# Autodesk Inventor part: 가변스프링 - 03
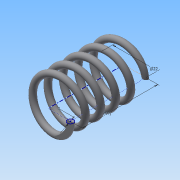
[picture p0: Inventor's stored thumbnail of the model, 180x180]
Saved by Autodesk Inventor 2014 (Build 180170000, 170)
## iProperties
Created: 2015-09
Part Number: 가변스프링 - 03
Material: 강철, 탄소
Document SubType Name: Modeling
Designer: study
Density: 1 g/cm^3
Appearance: 반연마
Mass: 2.38958 g
Surface Area: 32.4556 cm^2
Volume: 2.38958 cm^3
Author: study
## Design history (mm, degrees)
sketch "스케치1"
  geometry: L1 (0, 0)-(11, 0); L2 (11, 0)-(11, 29.193); L3 (11, 29.193)-(0, 29.193); L4 (0, 29.193)-(0, 0); C1 r 1.5 at (11, 0)
  constraints: 8 end point, 2 parallel, 1 centre point, 1 coincident, 1 horizontal, 1 perpendicular
  dimensions: "d0" = 22 diameter of L2 L4; "d1" = 29.19259 distance of L1.end L2.end (derived); "d2" = 3 diameter of C1
feature "코일1" sketch "스케치1" pitch "d3" = 10; turns "d5" = 5; dims "d4" = 29.19259 (= d1), "d6" = 0, angle "d7" = 90 deg, angle "d8" = 90 deg, "d9" = 0, "d10" = 0
node "작업 평면1"
sketch "스케치2"
  geometry: L1 (-12.5, 0)-(-9.5, 0) reference; 1 further point
  constraints: 1 horizontal alignment
extrude "돌출1" cut sketch "스케치2" stored distance "d12" = 10; taper "d13" = 0 deg
node "작업 평면2"
sketch "스케치3"
  geometry: L1 (-9.5, 0)-(-12.5, 0) reference; 1 further point
  constraints: 1 horizontal alignment
extrude "돌출2" cut sketch "스케치3" stored distance "d15" = 10; taper "d16" = 0 deg
node "솔리드1"
node "절단 모서리 투영1"
node "절단 모서리 투영2"
other parameters: "d11" = 0, "d14" = 29.19259 (= d1)
